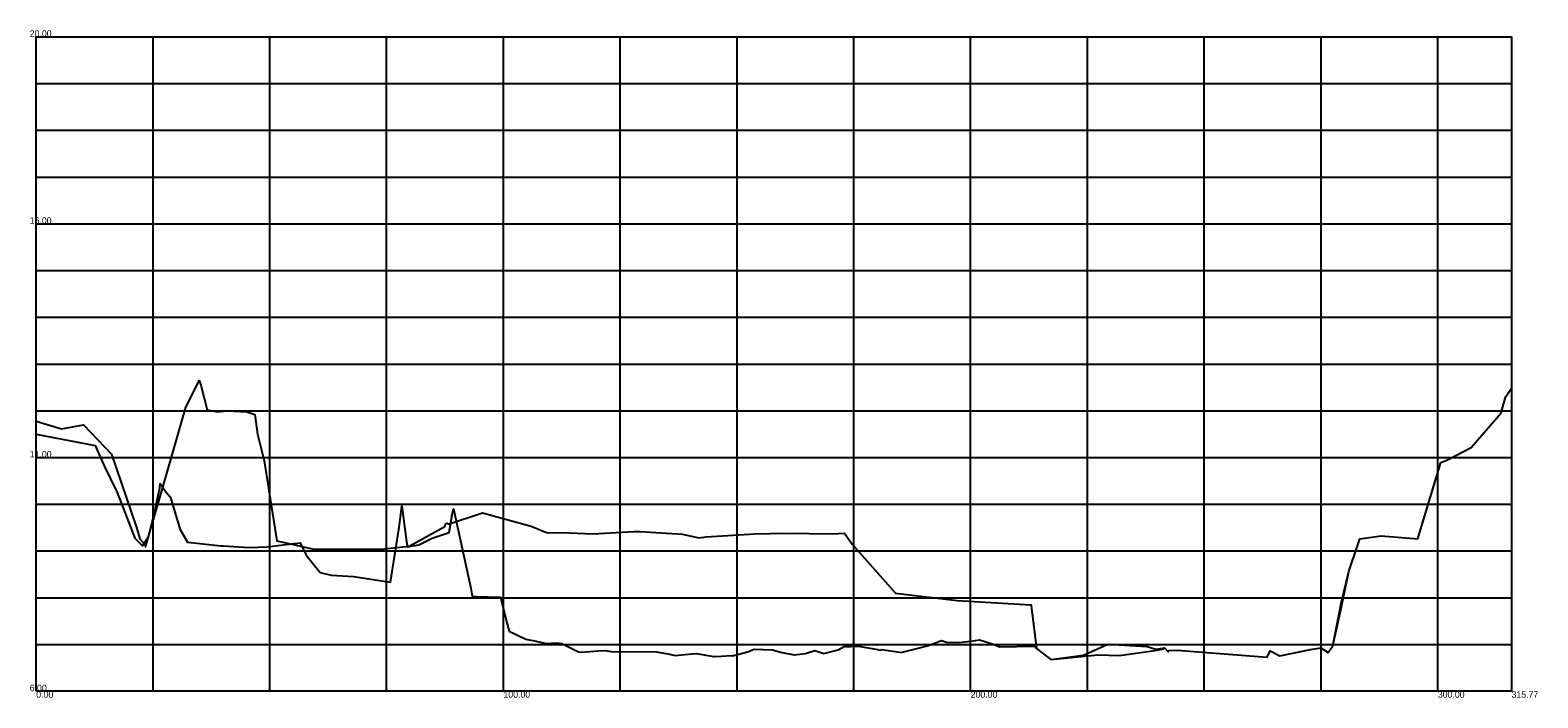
# Model space of a CAD drawing. Extents: x -1 to 1152, y 59 to 201.
# Drawn here: x 829.6 to 1152.3, y 58.6 to 201.4 of the extents above; entities that cross this region are included whole.
import ezdxf

# ---------------------------------------------------------------- set-up
doc = ezdxf.new("R2010")
doc.units = 0
doc.layers.add('MAAMUDEL', color=7, linetype='Continuous')

msp = doc.modelspace()

# ---------------------------------------------------------------- linework, layer by layer
at = {"layer": 'MAAMUDEL'}
for p, q in [((855.88, 60), (855.88, 200)), ((880.88, 60), (880.88, 200)), ((905.88, 60), (905.88, 200)), ((930.88, 60), (930.88, 200)), ((955.88, 60), (955.88, 200)), ((980.88, 60), (980.88, 200)), ((1005.88, 60), (1005.88, 200)), ((1030.88, 60), (1030.88, 200)), ((1055.88, 60), (1055.88, 200)), ((1080.88, 60), (1080.88, 200)), ((1105.88, 60), (1105.88, 200)), ((1130.88, 60), (1130.88, 200)), ((830.88, 190), (1146.65, 190)), ((830.88, 180), (1146.65, 180)), ((830.88, 170), (1146.65, 170)), ((830.88, 160), (1146.65, 160)), ((830.88, 150), (1146.65, 150)), ((830.88, 140), (1146.65, 140)), ((830.88, 130), (1146.65, 130)), ((830.88, 120), (1146.65, 120)), ((830.88, 110), (1146.65, 110)), ((830.88, 100), (1146.65, 100)), ((830.88, 90), (1146.65, 90)), ((830.88, 80), (1146.65, 80)), ((830.88, 70), (1146.65, 70))]:
    msp.add_line(p, q, dxfattribs=at)
msp.add_lwpolyline([(830.88, 60), (830.88, 200), (1146.65, 200), (1146.65, 60)], close=True, dxfattribs=at)
for points in [[(830.88, 117.78), (836.28, 116.13), (841, 117.01), (846.96, 110.72), (852.31, 95.05), (853.08, 92.59), (854.12, 91.4), (854.3, 90.88), (857.65, 102.36), (861.48, 115.77), (862.9, 120.73), (865.39, 125.69), (865.72, 126.48), (866.13, 125.5), (867.46, 120.2), (869.71, 119.8), (871.89, 120), (875.95, 119.75), (877.69, 119.19), (878.23, 114.97), (879.64, 109.25), (882.39, 92.2), (890.28, 90.41), (904.73, 90.38), (910.69, 91.05), (918.37, 95.26), (918.51, 95.81), (918.77, 95.92), (919.03, 95.7), (926.42, 98.14), (936.82, 95.3), (940.1, 93.94), (944.97, 93.85), (950.03, 93.68), (958.76, 94.13), (960.06, 94.16), (969.23, 93.56), (972.71, 92.79), (974.28, 93.05), (984.68, 93.65), (991.42, 93.8), (1001.31, 93.68), (1003.91, 93.84), (1005.19, 91.94), (1005.53, 91.45), (1014.77, 81), (1014.83, 80.99), (1028, 79.39), (1043.78, 78.5), (1043.82, 78.5), (1043.83, 78.45), (1043.86, 78.32), (1044.97, 69.16), (1048.02, 66.76), (1058.2, 67.8), (1062.72, 67.66), (1070.82, 68.81), (1072.16, 69.07), (1072.39, 69.25), (1073.18, 68.4), (1073.33, 68.7), (1074.98, 68.75), (1094.37, 67.26), (1094.96, 68.6), (1097.03, 67.56), (1103.61, 68.95), (1105.86, 69.26), (1107.4, 68.25), (1108.41, 69.67), (1109.86, 76.94), (1110.22, 78.8), (1111.85, 85.61), (1113.7, 91.13), (1114.16, 92.57), (1114.18, 92.58), (1118.75, 93.26), (1126.62, 92.59), (1126.93, 93.84), (1131.53, 108.93), (1132.08, 109.16), (1133.12, 109.54), (1137.98, 112.11), (1144.45, 119.58), (1145.36, 122.92), (1146.65, 124.84)], [(830.88, 114.97), (843.52, 112.57), (845.37, 108.38), (848.21, 102.51), (851.95, 92.77), (852.55, 92.18), (853.59, 91.07), (854.11, 91.98), (854.98, 93.21), (856.17, 98.15), (857.22, 102.84), (857.24, 102.96), (857.4, 104.44), (857.41, 104.43), (858, 103.59), (858.65, 102.65), (859.56, 101.59), (859.79, 100.91), (861.48, 95.26), (861.68, 94.59), (863.26, 91.87), (863.33, 91.87), (870.42, 91.07), (870.9, 91.08), (876.46, 90.73), (880.27, 90.91), (887.39, 91.73), (888.65, 89.09), (891.68, 85.42), (893.98, 84.83), (898.81, 84.52), (906.7, 83.33), (908.53, 95.04), (909.16, 99.6), (910.13, 91.92), (910.31, 90.91), (912.77, 91.34), (915.62, 92.74), (919.28, 93.98), (920.01, 98.14), (920.17, 99.04), (923.87, 82.07), (924.21, 80.34), (925.1, 80.25), (930.28, 80.13), (931.59, 74.62), (932.09, 72.86), (935.7, 71.16), (937.88, 70.71), (940.03, 70.2), (942.24, 70.37), (943.41, 70.22), (946.92, 68.41), (947.59, 68.35), (951.18, 68.66), (952.68, 68.73), (953.85, 68.52), (963.59, 68.45), (966.04, 67.96), (967.66, 67.67), (971.2, 68), (972.14, 68.07), (975.94, 67.43), (976.16, 67.43), (977.56, 67.48), (979.62, 67.64), (979.91, 67.55), (983.44, 68.5), (984.46, 68.99), (988.45, 68.88), (990.16, 68.36), (993.13, 67.75), (995.54, 68.05), (997.51, 68.73), (999.43, 68.08), (1002.53, 68.83), (1003.78, 69.53), (1005.19, 69.56), (1006.86, 69.6), (1011, 68.89), (1011.49, 68.76), (1011.87, 68.93), (1015.73, 68.34), (1016.15, 68.3), (1016.21, 68.33), (1021.65, 69.69), (1024.67, 70.86), (1025.9, 70.41), (1029.02, 70.5), (1030.94, 70.72), (1032.8, 70.98), (1035.54, 70.1), (1037.03, 69.49), (1044.42, 69.65), (1044.79, 69.47), (1044.97, 69.16), (1048.02, 66.76), (1055.02, 67.7), (1055.03, 67.7), (1055.04, 67.7), (1060.22, 70.05), (1068.69, 69.55), (1070.52, 69.02), (1072.39, 69.25), (1073.18, 68.4), (1073.33, 68.7), (1074.98, 68.75), (1094.37, 67.26), (1094.96, 68.6), (1097.03, 67.56), (1103.61, 68.95), (1105.86, 69.26), (1107.4, 68.25), (1108.41, 69.67), (1110.28, 78.07), (1111.85, 85.61), (1113.7, 91.13), (1114.16, 92.57), (1114.18, 92.58), (1118.75, 93.26), (1126.62, 92.59), (1126.93, 93.84), (1131.53, 108.93), (1132.08, 109.16), (1133.12, 109.54), (1137.98, 112.11), (1144.45, 119.58), (1145.36, 122.92), (1146.65, 124.84)], [(830.88, 114.97), (843.52, 112.57), (845.37, 108.38), (848.21, 102.51), (851.95, 92.77), (852.55, 92.18), (853.59, 91.07), (854.11, 91.98), (854.98, 93.21), (856.17, 98.15), (857.22, 102.84), (857.24, 102.96), (857.4, 104.44), (857.41, 104.43), (858, 103.59), (858.65, 102.65), (859.56, 101.59), (859.79, 100.91), (861.48, 95.26), (861.68, 94.59), (863.26, 91.87), (863.33, 91.87), (870.42, 91.07), (870.9, 91.08), (876.46, 90.73), (880.27, 90.91), (887.39, 91.73), (888.65, 89.09), (891.68, 85.42), (893.98, 84.83), (898.81, 84.52), (906.7, 83.33), (908.53, 95.04), (909.16, 99.6), (910.13, 91.92), (910.31, 90.91), (912.77, 91.34), (915.62, 92.74), (919.28, 93.98), (920.01, 98.14), (920.17, 99.04), (923.87, 82.07), (924.21, 80.34), (925.1, 80.25), (930.28, 80.13), (931.59, 74.62), (932.09, 72.86), (935.7, 71.16), (937.88, 70.71), (940.03, 70.2), (942.24, 70.37), (943.41, 70.22), (946.92, 68.41), (947.59, 68.35), (951.18, 68.66), (952.68, 68.73), (953.85, 68.52), (963.59, 68.45), (966.04, 67.96), (967.66, 67.67), (971.2, 68), (972.14, 68.07), (975.94, 67.43), (976.16, 67.43), (977.56, 67.48), (979.62, 67.64), (979.91, 67.55), (983.44, 68.5), (984.46, 68.99), (988.45, 68.88), (990.16, 68.36), (993.13, 67.75), (995.54, 68.05), (997.51, 68.73), (999.43, 68.08), (1002.53, 68.83), (1003.78, 69.53), (1005.19, 69.56), (1006.86, 69.6), (1011, 68.89), (1011.49, 68.76), (1011.87, 68.93), (1015.73, 68.34), (1016.15, 68.3), (1016.21, 68.33), (1021.65, 69.69), (1024.67, 70.86), (1025.9, 70.41), (1029.02, 70.5), (1030.94, 70.72), (1032.8, 70.98), (1035.54, 70.1), (1037.03, 69.49), (1044.42, 69.65), (1044.79, 69.47), (1044.97, 69.16), (1048.02, 66.76), (1055.02, 67.7), (1055.03, 67.7), (1055.04, 67.7), (1060.22, 70.05), (1068.69, 69.55), (1070.52, 69.02), (1072.39, 69.25), (1073.18, 68.4), (1073.33, 68.7), (1074.98, 68.75), (1094.37, 67.26), (1094.96, 68.6), (1097.03, 67.56), (1103.61, 68.95), (1105.86, 69.26), (1107.4, 68.25), (1108.41, 69.67), (1110.28, 78.07), (1111.85, 85.61), (1113.7, 91.13), (1114.16, 92.57), (1114.18, 92.58), (1118.75, 93.26), (1126.62, 92.59), (1126.93, 93.84), (1131.53, 108.93), (1132.08, 109.16), (1133.12, 109.54), (1137.98, 112.11), (1144.45, 119.58), (1145.36, 122.92), (1146.65, 124.84)]]:
    msp.add_lwpolyline(points, dxfattribs=at)

# ---------------------------------------------------------------- texts
for s, p in [('20.00', (829.48, 200)), ('16.00', (829.48, 160)), ('11.00', (829.48, 110)), ('6.00', (829.48, 60)), ('0.00', (830.88, 58.6)), ('100.00', (930.88, 58.6)), ('200.00', (1030.88, 58.6)), ('300.00', (1130.88, 58.6)), ('315.77', (1146.65, 58.6))]:
    msp.add_text(s, height=1.4, dxfattribs=at).set_placement(p)

doc.saveas('drawing.dxf')
